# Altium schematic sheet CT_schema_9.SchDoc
size 147 x 119 mm
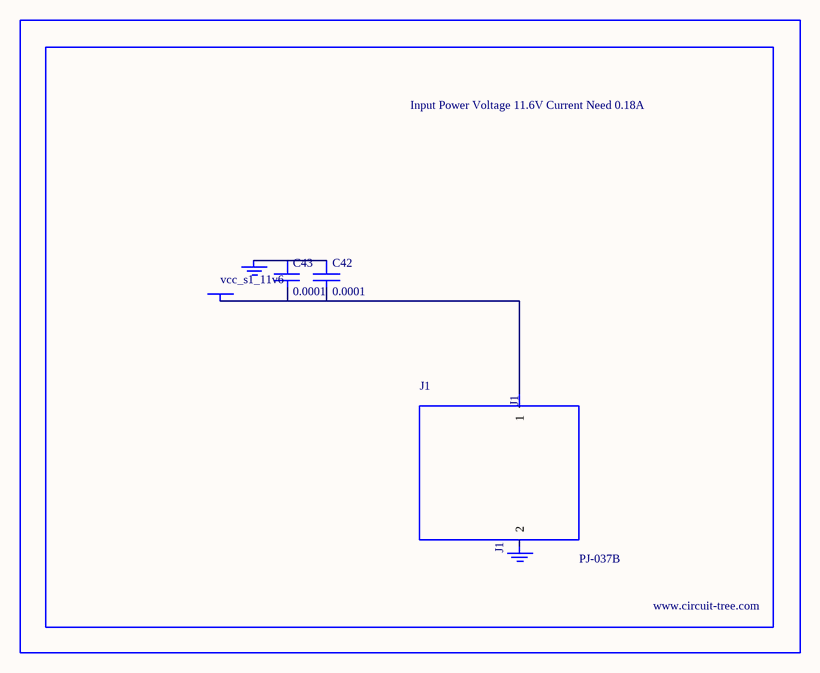
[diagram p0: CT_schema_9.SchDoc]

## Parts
BORDER8  (no value)
C42  0.0001  [EXV-9H]
C43  0.0001  [EXV-9H]
GND_INSTANCE_8_0  (no value)
GND_INSTANCE_8_1  (no value)
J1  PJ-037B  [PJ-037B_PACKAGE]
POWER_INSTANCE_8_0  vcc_s1_11v6

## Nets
NetC42_1: C42.1 C43.1 GND_INSTANCE_8_0.0(GND)
NetC42_2: C42.2 C43.2 J1.1 POWER_INSTANCE_8_0.0(PWR)

Not connected (* = marked no-connect by the designer): GND_INSTANCE_8_1 0(GND); J1 2

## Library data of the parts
BORDER8 = BORDER_PAGE8
C42 C43 = EDK107M035A9HAA
GND_INSTANCE_8_0 GND_INSTANCE_8_1 = GND
POWER_INSTANCE_8_0 = PWR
